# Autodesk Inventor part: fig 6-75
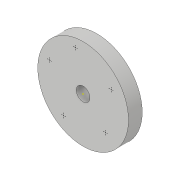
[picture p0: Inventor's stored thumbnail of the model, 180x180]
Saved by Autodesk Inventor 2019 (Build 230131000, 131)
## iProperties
Created: 2018-03
Part Number: fig 6-75
Material: Generic
Document SubType Name: Modeling
Designer: CADCIM 00
Density: 1 g/cm^3
Appearance: Default
Author: CADCIM 00
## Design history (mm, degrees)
sketch "Sketch1"
  geometry: C1 r 16.506 at (0, 0); 1 further point
  constraints: 1 centre point, 1 coincident
extrude "Extrusion1" new body sketch "Sketch1" distance "d0" = 5; taper "d1" = 0 deg
sketch "Sketch3"
  geometry: 2 further points
  constraints: 1 coincident
hole "Hole1" sketch "Sketch3" at (0, 0) diameter "d2" = 5; stored, may be unused: countersink angle "d6" = 90 deg, drill point angle "d8" = 118 deg; dims "d3" = 6, "d4" = 4, "d5" = 2, "d7" = 8
sketch "Sketch2"
  geometry: 6 further points
body "Solid1"
